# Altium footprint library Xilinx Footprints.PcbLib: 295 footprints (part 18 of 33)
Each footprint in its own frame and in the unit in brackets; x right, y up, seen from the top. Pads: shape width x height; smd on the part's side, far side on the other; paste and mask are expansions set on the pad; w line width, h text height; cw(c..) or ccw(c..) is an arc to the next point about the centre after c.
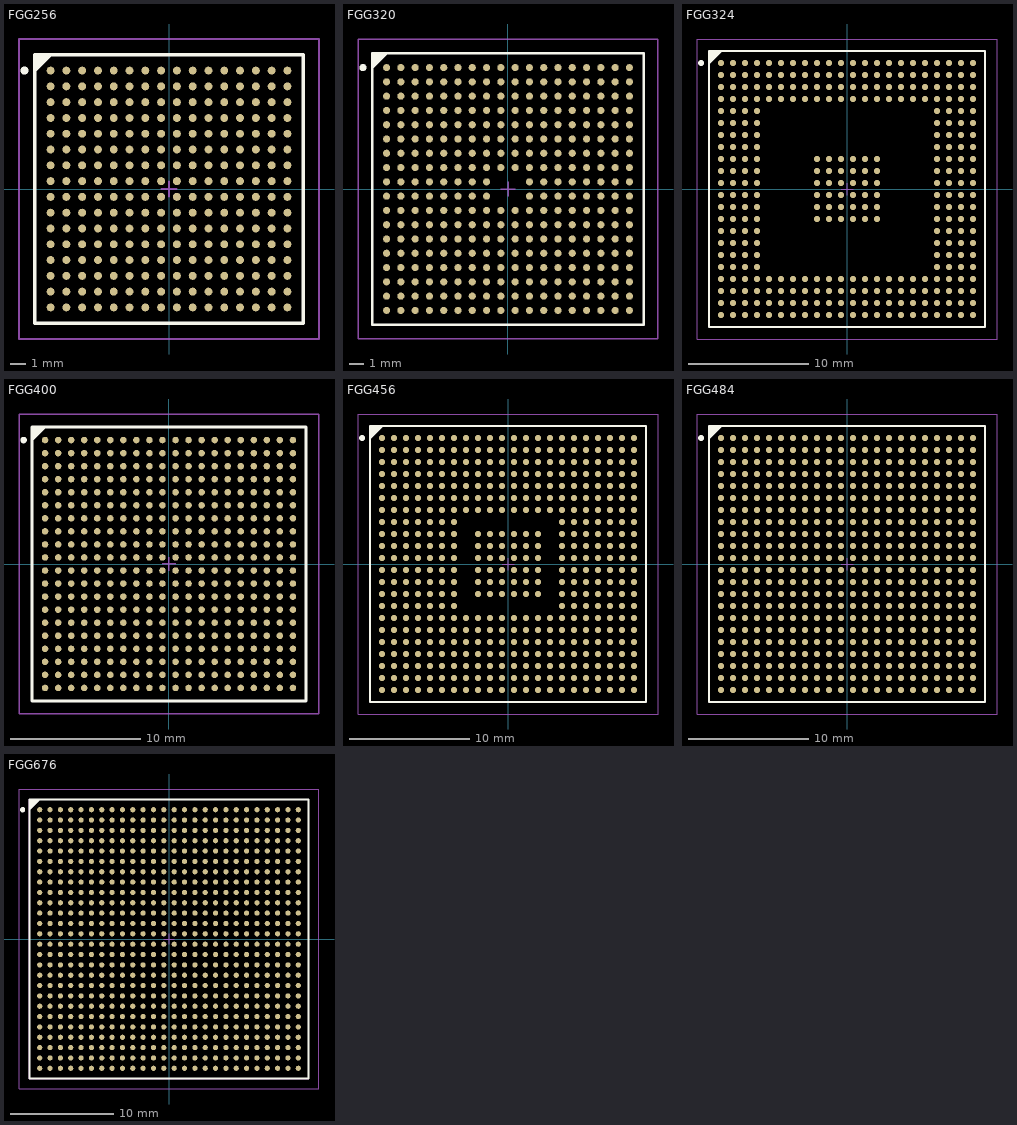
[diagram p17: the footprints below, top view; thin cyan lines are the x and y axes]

## FGG256 [mm] "256-Ball Fine Pitch Ball Grid Array (FGG256) - Pb-Free"
height 2
pads (256):
  round 0.5 smd: A1(-7.5,7.5) A2(-6.5,7.5) A3(-5.5,7.5) A4(-4.5,7.5) A5(-3.5,7.5) A6(-2.5,7.5) A7(-1.5,7.5) A8(-0.5,7.5) A9(0.5,7.5) A10(1.5,7.5) A11(2.5,7.5) A12(3.5,7.5) A13(4.5,7.5) A14(5.5,7.5) A15(6.5,7.5) A16(7.5,7.5) B1(-7.5,6.5) B2(-6.5,6.5) B3(-5.5,6.5) B4(-4.5,6.5) B5(-3.5,6.5) B6(-2.5,6.5) B7(-1.5,6.5) B8(-0.5,6.5) B9(0.5,6.5) B10(1.5,6.5) B11(2.5,6.5) B12(3.5,6.5) B13(4.5,6.5) B14(5.5,6.5) B15(6.5,6.5) B16(7.5,6.5) C1(-7.5,5.5) C2(-6.5,5.5) C3(-5.5,5.5) C4(-4.5,5.5) C5(-3.5,5.5) C6(-2.5,5.5) C7(-1.5,5.5) C8(-0.5,5.5) C9(0.5,5.5) C10(1.5,5.5) C11(2.5,5.5) C12(3.5,5.5) C13(4.5,5.5) C14(5.5,5.5) C15(6.5,5.5) C16(7.5,5.5) D1(-7.5,4.5) D2(-6.5,4.5) D3(-5.5,4.5) D4(-4.5,4.5) D5(-3.5,4.5) D6(-2.5,4.5) D7(-1.5,4.5) D8(-0.5,4.5) D9(0.5,4.5) D10(1.5,4.5) D11(2.5,4.5) D12(3.5,4.5) D13(4.5,4.5) D14(5.5,4.5) D15(6.5,4.5) D16(7.5,4.5) E1(-7.5,3.5) E2(-6.5,3.5) E3(-5.5,3.5) E4(-4.5,3.5) E5(-3.5,3.5) E6(-2.5,3.5) E7(-1.5,3.5) E8(-0.5,3.5) E9(0.5,3.5) E10(1.5,3.5) E11(2.5,3.5) E12(3.5,3.5) E13(4.5,3.5) E14(5.5,3.5) E15(6.5,3.5) E16(7.5,3.5) F1(-7.5,2.5) F2(-6.5,2.5) F3(-5.5,2.5) F4(-4.5,2.5) F5(-3.5,2.5) F6(-2.5,2.5) F7(-1.5,2.5) F8(-0.5,2.5) F9(0.5,2.5) F10(1.5,2.5) F11(2.5,2.5) F12(3.5,2.5) F13(4.5,2.5) F14(5.5,2.5) F15(6.5,2.5) F16(7.5,2.5) G1(-7.5,1.5) G2(-6.5,1.5) G3(-5.5,1.5) G4(-4.5,1.5) G5(-3.5,1.5) G6(-2.5,1.5) G7(-1.5,1.5) G8(-0.5,1.5) G9(0.5,1.5) G10(1.5,1.5) G11(2.5,1.5) G12(3.5,1.5) G13(4.5,1.5) G14(5.5,1.5) G15(6.5,1.5) G16(7.5,1.5) H1(-7.5,0.5) H2(-6.5,0.5) H3(-5.5,0.5) H4(-4.5,0.5) H5(-3.5,0.5) H6(-2.5,0.5) H7(-1.5,0.5) H8(-0.5,0.5) H9(0.5,0.5) H10(1.5,0.5) H11(2.5,0.5) H12(3.5,0.5) H13(4.5,0.5) H14(5.5,0.5) H15(6.5,0.5) H16(7.5,0.5) J1(-7.5,-0.5) J2(-6.5,-0.5) J3(-5.5,-0.5) J4(-4.5,-0.5) J5(-3.5,-0.5) J6(-2.5,-0.5) J7(-1.5,-0.5) J8(-0.5,-0.5) J9(0.5,-0.5) J10(1.5,-0.5) J11(2.5,-0.5) J12(3.5,-0.5) J13(4.5,-0.5) J14(5.5,-0.5) J15(6.5,-0.5) J16(7.5,-0.5) K1(-7.5,-1.5) K2(-6.5,-1.5) K3(-5.5,-1.5) K4(-4.5,-1.5) K5(-3.5,-1.5) K6(-2.5,-1.5) K7(-1.5,-1.5) K8(-0.5,-1.5) K9(0.5,-1.5) K10(1.5,-1.5) K11(2.5,-1.5) K12(3.5,-1.5) K13(4.5,-1.5) K14(5.5,-1.5) K15(6.5,-1.5) K16(7.5,-1.5) L1(-7.5,-2.5) L2(-6.5,-2.5) L3(-5.5,-2.5) L4(-4.5,-2.5) L5(-3.5,-2.5) L6(-2.5,-2.5) L7(-1.5,-2.5) L8(-0.5,-2.5) L9(0.5,-2.5) L10(1.5,-2.5) L11(2.5,-2.5) L12(3.5,-2.5) L13(4.5,-2.5) L14(5.5,-2.5) L15(6.5,-2.5) L16(7.5,-2.5) M1(-7.5,-3.5) M2(-6.5,-3.5) M3(-5.5,-3.5) M4(-4.5,-3.5) M5(-3.5,-3.5) M6(-2.5,-3.5) M7(-1.5,-3.5) M8(-0.5,-3.5) M9(0.5,-3.5) M10(1.5,-3.5) M11(2.5,-3.5) M12(3.5,-3.5) M13(4.5,-3.5) M14(5.5,-3.5) M15(6.5,-3.5) M16(7.5,-3.5) N1(-7.5,-4.5) N2(-6.5,-4.5) N3(-5.5,-4.5) N4(-4.5,-4.5) N5(-3.5,-4.5) N6(-2.5,-4.5) N7(-1.5,-4.5) N8(-0.5,-4.5) N9(0.5,-4.5) N10(1.5,-4.5) N11(2.5,-4.5) N12(3.5,-4.5) N13(4.5,-4.5) N14(5.5,-4.5) N15(6.5,-4.5) N16(7.5,-4.5) P1(-7.5,-5.5) P2(-6.5,-5.5) P3(-5.5,-5.5) P4(-4.5,-5.5) P5(-3.5,-5.5) P6(-2.5,-5.5) P7(-1.5,-5.5) P8(-0.5,-5.5) P9(0.5,-5.5) P10(1.5,-5.5) P11(2.5,-5.5) P12(3.5,-5.5) P13(4.5,-5.5) P14(5.5,-5.5) P15(6.5,-5.5) P16(7.5,-5.5) R1(-7.5,-6.5) R2(-6.5,-6.5) R3(-5.5,-6.5) R4(-4.5,-6.5) R5(-3.5,-6.5) R6(-2.5,-6.5) R7(-1.5,-6.5) R8(-0.5,-6.5) R9(0.5,-6.5) R10(1.5,-6.5) R11(2.5,-6.5) R12(3.5,-6.5) R13(4.5,-6.5) R14(5.5,-6.5) R15(6.5,-6.5) R16(7.5,-6.5) T1(-7.5,-7.5) T2(-6.5,-7.5) T3(-5.5,-7.5) T4(-4.5,-7.5) T5(-3.5,-7.5) T6(-2.5,-7.5) T7(-1.5,-7.5) T8(-0.5,-7.5) T9(0.5,-7.5) T10(1.5,-7.5) T11(2.5,-7.5) T12(3.5,-7.5) T13(4.5,-7.5) T14(5.5,-7.5) T15(6.5,-7.5) T16(7.5,-7.5)
Top Overlay:
  circle w0.25: c-9.15,7.5 r0.125
  region: -7.5,8.5 -8.5,7.5 -8.5,8.5
  lines w0.2: -8.5,7.5 -7.5,8.5 ; -8.5,-8.5 -8.5,8.5 8.5,8.5 8.5,-8.5 -8.5,-8.5
Mechanical 13:
  lines w0.1: -8.5,-8.5 -8.5,8.5 8.5,8.5 8.5,-8.5 -8.5,-8.5
Mechanical 15:
  lines w0.1: -0.5,0 0.5,0 ; 0,-0.5 0,0.5 ; -9.5,-9.5 -9.5,9.5 9.5,9.5 9.5,-9.5 -9.5,-9.5
3D body: height 2, standoff 0, extent -8.5,-8.5 8.5,8.5

## FGG320 [mm] "320-Ball Fine Pitch Ball Grid Array (FGG320) - Pb-Free"
height 2
pads (320):
  round 0.5 smd: A1(-8.5,8.5) A2(-7.5,8.5) A3(-6.5,8.5) A4(-5.5,8.5) A5(-4.5,8.5) A6(-3.5,8.5) A7(-2.5,8.5) A8(-1.5,8.5) A9(-0.5,8.5) A10(0.5,8.5) A11(1.5,8.5) A12(2.5,8.5) A13(3.5,8.5) A14(4.5,8.5) A15(5.5,8.5) A16(6.5,8.5) A17(7.5,8.5) A18(8.5,8.5) B1(-8.5,7.5) B2(-7.5,7.5) B3(-6.5,7.5) B4(-5.5,7.5) B5(-4.5,7.5) B6(-3.5,7.5) B7(-2.5,7.5) B8(-1.5,7.5) B9(-0.5,7.5) B10(0.5,7.5) B11(1.5,7.5) B12(2.5,7.5) B13(3.5,7.5) B14(4.5,7.5) B15(5.5,7.5) B16(6.5,7.5) B17(7.5,7.5) B18(8.5,7.5) C1(-8.5,6.5) C2(-7.5,6.5) C3(-6.5,6.5) C4(-5.5,6.5) C5(-4.5,6.5) C6(-3.5,6.5) C7(-2.5,6.5) C8(-1.5,6.5) C9(-0.5,6.5) C10(0.5,6.5) C11(1.5,6.5) C12(2.5,6.5) C13(3.5,6.5) C14(4.5,6.5) C15(5.5,6.5) C16(6.5,6.5) C17(7.5,6.5) C18(8.5,6.5) D1(-8.5,5.5) D2(-7.5,5.5) D3(-6.5,5.5) D4(-5.5,5.5) D5(-4.5,5.5) D6(-3.5,5.5) D7(-2.5,5.5) D8(-1.5,5.5) D9(-0.5,5.5) D10(0.5,5.5) D11(1.5,5.5) D12(2.5,5.5) D13(3.5,5.5) D14(4.5,5.5) D15(5.5,5.5) D16(6.5,5.5) D17(7.5,5.5) D18(8.5,5.5) E1(-8.5,4.5) E2(-7.5,4.5) E3(-6.5,4.5) E4(-5.5,4.5) E5(-4.5,4.5) E6(-3.5,4.5) E7(-2.5,4.5) E8(-1.5,4.5) E9(-0.5,4.5) E10(0.5,4.5) E11(1.5,4.5) E12(2.5,4.5) E13(3.5,4.5) E14(4.5,4.5) E15(5.5,4.5) E16(6.5,4.5) E17(7.5,4.5) E18(8.5,4.5) F1(-8.5,3.5) F2(-7.5,3.5) F3(-6.5,3.5) F4(-5.5,3.5) F5(-4.5,3.5) F6(-3.5,3.5) F7(-2.5,3.5) F8(-1.5,3.5) F9(-0.5,3.5) F10(0.5,3.5) F11(1.5,3.5) F12(2.5,3.5) F13(3.5,3.5) F14(4.5,3.5) F15(5.5,3.5) F16(6.5,3.5) F17(7.5,3.5) F18(8.5,3.5) G1(-8.5,2.5) G2(-7.5,2.5) G3(-6.5,2.5) G4(-5.5,2.5) G5(-4.5,2.5) G6(-3.5,2.5) G7(-2.5,2.5) G8(-1.5,2.5) G9(-0.5,2.5) G10(0.5,2.5) G11(1.5,2.5) G12(2.5,2.5) G13(3.5,2.5) G14(4.5,2.5) G15(5.5,2.5) G16(6.5,2.5) G17(7.5,2.5) G18(8.5,2.5) H1(-8.5,1.5) H2(-7.5,1.5) H3(-6.5,1.5) H4(-5.5,1.5) H5(-4.5,1.5) H6(-3.5,1.5) H7(-2.5,1.5) H8(-1.5,1.5) H9(-0.5,1.5) H10(0.5,1.5) H11(1.5,1.5) H12(2.5,1.5) H13(3.5,1.5) H14(4.5,1.5) H15(5.5,1.5) H16(6.5,1.5) H17(7.5,1.5) H18(8.5,1.5) J1(-8.5,0.5) J2(-7.5,0.5) J3(-6.5,0.5) J4(-5.5,0.5) J5(-4.5,0.5) J6(-3.5,0.5) J7(-2.5,0.5) J8(-1.5,0.5) J11(1.5,0.5) J12(2.5,0.5) J13(3.5,0.5) J14(4.5,0.5) J15(5.5,0.5) J16(6.5,0.5) J17(7.5,0.5) J18(8.5,0.5) K1(-8.5,-0.5) K2(-7.5,-0.5) K3(-6.5,-0.5) K4(-5.5,-0.5) K5(-4.5,-0.5) K6(-3.5,-0.5) K7(-2.5,-0.5) K8(-1.5,-0.5) K11(1.5,-0.5) K12(2.5,-0.5) K13(3.5,-0.5) K14(4.5,-0.5) K15(5.5,-0.5) K16(6.5,-0.5) K17(7.5,-0.5) K18(8.5,-0.5) L1(-8.5,-1.5) L2(-7.5,-1.5) L3(-6.5,-1.5) L4(-5.5,-1.5) L5(-4.5,-1.5) L6(-3.5,-1.5) L7(-2.5,-1.5) L8(-1.5,-1.5) L9(-0.5,-1.5) L10(0.5,-1.5) L11(1.5,-1.5) L12(2.5,-1.5) L13(3.5,-1.5) L14(4.5,-1.5) L15(5.5,-1.5) L16(6.5,-1.5) L17(7.5,-1.5) L18(8.5,-1.5) M1(-8.5,-2.5) M2(-7.5,-2.5) M3(-6.5,-2.5) M4(-5.5,-2.5) M5(-4.5,-2.5) M6(-3.5,-2.5) M7(-2.5,-2.5) M8(-1.5,-2.5) M9(-0.5,-2.5) M10(0.5,-2.5) M11(1.5,-2.5) M12(2.5,-2.5) M13(3.5,-2.5) M14(4.5,-2.5) M15(5.5,-2.5) M16(6.5,-2.5) M17(7.5,-2.5) M18(8.5,-2.5) N1(-8.5,-3.5) N2(-7.5,-3.5) N3(-6.5,-3.5) N4(-5.5,-3.5) N5(-4.5,-3.5) N6(-3.5,-3.5) N7(-2.5,-3.5) N8(-1.5,-3.5) N9(-0.5,-3.5) N10(0.5,-3.5) N11(1.5,-3.5) N12(2.5,-3.5) N13(3.5,-3.5) N14(4.5,-3.5) N15(5.5,-3.5) N16(6.5,-3.5) N17(7.5,-3.5) N18(8.5,-3.5) P1(-8.5,-4.5) P2(-7.5,-4.5) P3(-6.5,-4.5) P4(-5.5,-4.5) P5(-4.5,-4.5) P6(-3.5,-4.5) P7(-2.5,-4.5) P8(-1.5,-4.5) P9(-0.5,-4.5) P10(0.5,-4.5) P11(1.5,-4.5) P12(2.5,-4.5) P13(3.5,-4.5) P14(4.5,-4.5) P15(5.5,-4.5) P16(6.5,-4.5) P17(7.5,-4.5) P18(8.5,-4.5) R1(-8.5,-5.5) R2(-7.5,-5.5) R3(-6.5,-5.5) R4(-5.5,-5.5) R5(-4.5,-5.5) R6(-3.5,-5.5) R7(-2.5,-5.5) R8(-1.5,-5.5) R9(-0.5,-5.5) R10(0.5,-5.5) R11(1.5,-5.5) R12(2.5,-5.5) R13(3.5,-5.5) R14(4.5,-5.5) R15(5.5,-5.5) R16(6.5,-5.5) R17(7.5,-5.5) R18(8.5,-5.5) T1(-8.5,-6.5) T2(-7.5,-6.5) T3(-6.5,-6.5) T4(-5.5,-6.5) T5(-4.5,-6.5) T6(-3.5,-6.5) T7(-2.5,-6.5) T8(-1.5,-6.5) T9(-0.5,-6.5) T10(0.5,-6.5) T11(1.5,-6.5) T12(2.5,-6.5) T13(3.5,-6.5) T14(4.5,-6.5) T15(5.5,-6.5) T16(6.5,-6.5) T17(7.5,-6.5) T18(8.5,-6.5) U1(-8.5,-7.5) U2(-7.5,-7.5) U3(-6.5,-7.5) U4(-5.5,-7.5) U5(-4.5,-7.5) U6(-3.5,-7.5) U7(-2.5,-7.5) U8(-1.5,-7.5) U9(-0.5,-7.5) U10(0.5,-7.5) U11(1.5,-7.5) U12(2.5,-7.5) U13(3.5,-7.5) U14(4.5,-7.5) U15(5.5,-7.5) U16(6.5,-7.5) U17(7.5,-7.5) U18(8.5,-7.5) V1(-8.5,-8.5) V2(-7.5,-8.5) V3(-6.5,-8.5) V4(-5.5,-8.5) V5(-4.5,-8.5) V6(-3.5,-8.5) V7(-2.5,-8.5) V8(-1.5,-8.5) V9(-0.5,-8.5) V10(0.5,-8.5) V11(1.5,-8.5) V12(2.5,-8.5) V13(3.5,-8.5) V14(4.5,-8.5) V15(5.5,-8.5) V16(6.5,-8.5) V17(7.5,-8.5) V18(8.5,-8.5)
Top Overlay:
  circle w0.25: c-10.15,8.5 r0.125
  region: -8.5,9.5 -9.5,8.5 -9.5,9.5
  lines w0.2: -9.5,8.5 -8.5,9.5 ; -9.5,-9.5 9.5,-9.5 9.5,9.5 -9.5,9.5 -9.5,-9.5
Mechanical 13:
  lines w0.1: -9.5,-9.5 9.5,-9.5 9.5,9.5 -9.5,9.5 -9.5,-9.5
Mechanical 15:
  lines w0.1: -0.5,0 0.5,0 ; 0,-0.5 0,0.5 ; -10.5,-10.5 10.5,-10.5 10.5,10.5 -10.5,10.5 -10.5,-10.5
3D body: height 2, standoff 0, extent -9.5,-9.5 9.5,9.5

## FGG324 [mm] "324-Ball Fine Pitch Ball Grid Array 1.00 mm Pitch (FGG324) - Pb-Free"
height 2.5
pads (324):
  round 0.5 smd: A1(-10.5,10.5) A2(-9.5,10.5) A3(-8.5,10.5) A4(-7.5,10.5) A5(-6.5,10.5) A6(-5.5,10.5) A7(-4.5,10.5) A8(-3.5,10.5) A9(-2.5,10.5) A10(-1.5,10.5) A11(-0.5,10.5) A12(0.5,10.5) A13(1.5,10.5) A14(2.5,10.5) A15(3.5,10.5) A16(4.5,10.5) A17(5.5,10.5) A18(6.5,10.5) A19(7.5,10.5) A20(8.5,10.5) A21(9.5,10.5) A22(10.5,10.5) AA1(-10.5,-9.5) AA2(-9.5,-9.5) AA3(-8.5,-9.5) AA4(-7.5,-9.5) AA5(-6.5,-9.5) AA6(-5.5,-9.5) AA7(-4.5,-9.5) AA8(-3.5,-9.5) AA9(-2.5,-9.5) AA10(-1.5,-9.5) AA11(-0.5,-9.5) AA12(0.5,-9.5) AA13(1.5,-9.5) AA14(2.5,-9.5) AA15(3.5,-9.5) AA16(4.5,-9.5) AA17(5.5,-9.5) AA18(6.5,-9.5) AA19(7.5,-9.5) AA20(8.5,-9.5) AA21(9.5,-9.5) AA22(10.5,-9.5) AB1(-10.5,-10.5) AB2(-9.5,-10.5) AB3(-8.5,-10.5) AB4(-7.5,-10.5) AB5(-6.5,-10.5) AB6(-5.5,-10.5) AB7(-4.5,-10.5) AB8(-3.5,-10.5) AB9(-2.5,-10.5) AB10(-1.5,-10.5) AB11(-0.5,-10.5) AB12(0.5,-10.5) AB13(1.5,-10.5) AB14(2.5,-10.5) AB15(3.5,-10.5) AB16(4.5,-10.5) AB17(5.5,-10.5) AB18(6.5,-10.5) AB19(7.5,-10.5) AB20(8.5,-10.5) AB21(9.5,-10.5) AB22(10.5,-10.5) B1(-10.5,9.5) B2(-9.5,9.5) B3(-8.5,9.5) B4(-7.5,9.5) B5(-6.5,9.5) B6(-5.5,9.5) B7(-4.5,9.5) B8(-3.5,9.5) B9(-2.5,9.5) B10(-1.5,9.5) B11(-0.5,9.5) B12(0.5,9.5) B13(1.5,9.5) B14(2.5,9.5) B15(3.5,9.5) B16(4.5,9.5) B17(5.5,9.5) B18(6.5,9.5) B19(7.5,9.5) B20(8.5,9.5) B21(9.5,9.5) B22(10.5,9.5) C1(-10.5,8.5) C2(-9.5,8.5) C3(-8.5,8.5) C4(-7.5,8.5) C5(-6.5,8.5) C6(-5.5,8.5) C7(-4.5,8.5) C8(-3.5,8.5) C9(-2.5,8.5) C10(-1.5,8.5) C11(-0.5,8.5) C12(0.5,8.5) C13(1.5,8.5) C14(2.5,8.5) C15(3.5,8.5) C16(4.5,8.5) C17(5.5,8.5) C18(6.5,8.5) C19(7.5,8.5) C20(8.5,8.5) C21(9.5,8.5) C22(10.5,8.5) D1(-10.5,7.5) D2(-9.5,7.5) D3(-8.5,7.5) D4(-7.5,7.5) D5(-6.5,7.5) D6(-5.5,7.5) D7(-4.5,7.5) D8(-3.5,7.5) D9(-2.5,7.5) D10(-1.5,7.5) D11(-0.5,7.5) D12(0.5,7.5) D13(1.5,7.5) D14(2.5,7.5) D15(3.5,7.5) D16(4.5,7.5) D17(5.5,7.5) D18(6.5,7.5) D19(7.5,7.5) D20(8.5,7.5) D21(9.5,7.5) D22(10.5,7.5) E1(-10.5,6.5) E2(-9.5,6.5) E3(-8.5,6.5) E4(-7.5,6.5) E19(7.5,6.5) E20(8.5,6.5) E21(9.5,6.5) E22(10.5,6.5) F1(-10.5,5.5) F2(-9.5,5.5) F3(-8.5,5.5) F4(-7.5,5.5) F19(7.5,5.5) F20(8.5,5.5) F21(9.5,5.5) F22(10.5,5.5) G1(-10.5,4.5) G2(-9.5,4.5) G3(-8.5,4.5) G4(-7.5,4.5) G19(7.5,4.5) G20(8.5,4.5) G21(9.5,4.5) G22(10.5,4.5) H1(-10.5,3.5) H2(-9.5,3.5) H3(-8.5,3.5) H4(-7.5,3.5) H19(7.5,3.5) H20(8.5,3.5) H21(9.5,3.5) H22(10.5,3.5) J1(-10.5,2.5) J2(-9.5,2.5) J3(-8.5,2.5) J4(-7.5,2.5) J9(-2.5,2.5) J10(-1.5,2.5) J11(-0.5,2.5) J12(0.5,2.5) J13(1.5,2.5) J14(2.5,2.5) J19(7.5,2.5) J20(8.5,2.5) J21(9.5,2.5) J22(10.5,2.5) K1(-10.5,1.5) K2(-9.5,1.5) K3(-8.5,1.5) K4(-7.5,1.5) K9(-2.5,1.5) K10(-1.5,1.5) K11(-0.5,1.5) K12(0.5,1.5) K13(1.5,1.5) K14(2.5,1.5) K19(7.5,1.5) K20(8.5,1.5) K21(9.5,1.5) K22(10.5,1.5) L1(-10.5,0.5) L2(-9.5,0.5) L3(-8.5,0.5) L4(-7.5,0.5) L9(-2.5,0.5) L10(-1.5,0.5) L11(-0.5,0.5) L12(0.5,0.5) L13(1.5,0.5) L14(2.5,0.5) L19(7.5,0.5) L20(8.5,0.5) L21(9.5,0.5) L22(10.5,0.5) M1(-10.5,-0.5) M2(-9.5,-0.5) M3(-8.5,-0.5) M4(-7.5,-0.5) M9(-2.5,-0.5) M10(-1.5,-0.5) M11(-0.5,-0.5) M12(0.5,-0.5) M13(1.5,-0.5) M14(2.5,-0.5) M19(7.5,-0.5) M20(8.5,-0.5) M21(9.5,-0.5) M22(10.5,-0.5) N1(-10.5,-1.5) N2(-9.5,-1.5) N3(-8.5,-1.5) N4(-7.5,-1.5) N9(-2.5,-1.5) N10(-1.5,-1.5) N11(-0.5,-1.5) N12(0.5,-1.5) N13(1.5,-1.5) N14(2.5,-1.5) N19(7.5,-1.5) N20(8.5,-1.5) N21(9.5,-1.5) N22(10.5,-1.5) P1(-10.5,-2.5) P2(-9.5,-2.5) P3(-8.5,-2.5) P4(-7.5,-2.5) P9(-2.5,-2.5) P10(-1.5,-2.5) P11(-0.5,-2.5) P12(0.5,-2.5) P13(1.5,-2.5) P14(2.5,-2.5) P19(7.5,-2.5) P20(8.5,-2.5) P21(9.5,-2.5) P22(10.5,-2.5) R1(-10.5,-3.5) R2(-9.5,-3.5) R3(-8.5,-3.5) R4(-7.5,-3.5) R19(7.5,-3.5) R20(8.5,-3.5) R21(9.5,-3.5) R22(10.5,-3.5) T1(-10.5,-4.5) T2(-9.5,-4.5) T3(-8.5,-4.5) T4(-7.5,-4.5) T19(7.5,-4.5) T20(8.5,-4.5) T21(9.5,-4.5) T22(10.5,-4.5) U1(-10.5,-5.5) U2(-9.5,-5.5) U3(-8.5,-5.5) U4(-7.5,-5.5) U19(7.5,-5.5) U20(8.5,-5.5) U21(9.5,-5.5) U22(10.5,-5.5) V1(-10.5,-6.5) V2(-9.5,-6.5) V3(-8.5,-6.5) V4(-7.5,-6.5) V19(7.5,-6.5) V20(8.5,-6.5) V21(9.5,-6.5) V22(10.5,-6.5) W1(-10.5,-7.5) W2(-9.5,-7.5) W3(-8.5,-7.5) W4(-7.5,-7.5) W5(-6.5,-7.5) W6(-5.5,-7.5) W7(-4.5,-7.5) W8(-3.5,-7.5) W9(-2.5,-7.5) W10(-1.5,-7.5) W11(-0.5,-7.5) W12(0.5,-7.5) W13(1.5,-7.5) W14(2.5,-7.5) W15(3.5,-7.5) W16(4.5,-7.5) W17(5.5,-7.5) W18(6.5,-7.5) W19(7.5,-7.5) W20(8.5,-7.5) W21(9.5,-7.5) W22(10.5,-7.5) Y1(-10.5,-8.5) Y2(-9.5,-8.5) Y3(-8.5,-8.5) Y4(-7.5,-8.5) Y5(-6.5,-8.5) Y6(-5.5,-8.5) Y7(-4.5,-8.5) Y8(-3.5,-8.5) Y9(-2.5,-8.5) Y10(-1.5,-8.5) Y11(-0.5,-8.5) Y12(0.5,-8.5) Y13(1.5,-8.5) Y14(2.5,-8.5) Y15(3.5,-8.5) Y16(4.5,-8.5) Y17(5.5,-8.5) Y18(6.5,-8.5) Y19(7.5,-8.5) Y20(8.5,-8.5) Y21(9.5,-8.5) Y22(10.5,-8.5)
Top Overlay:
  circle w0.25: c-12.15,10.5 r0.125
  region: -10.5,11.5 -11.5,10.5 -11.5,11.5
  lines w0.2: -11.5,10.5 -10.5,11.5 ; -11.5,-11.5 11.5,-11.5 11.5,11.5 -11.5,11.5 -11.5,-11.5
Mechanical 13:
  lines w0.1: -11.5,-11.5 11.5,-11.5 11.5,11.5 -11.5,11.5 -11.5,-11.5
Mechanical 15:
  lines w0.1: -0.5,0 0.5,0 ; 0,-0.5 0,0.5 ; -12.5,-12.5 12.5,-12.5 12.5,12.5 -12.5,12.5 -12.5,-12.5
3D body: height 2.5, standoff 0, extent -11.5,-11.5 11.5,11.5

## FGG400 [mm] "400-Ball Fine Pitch Ball Grid Array 1.00 mm Pitch (FGG400) - Pb-Free"
height 2.43
pads (400):
  round 0.5 smd: A1(-9.5,9.5) A2(-8.5,9.5) A3(-7.5,9.5) A4(-6.5,9.5) A5(-5.5,9.5) A6(-4.5,9.5) A7(-3.5,9.5) A8(-2.5,9.5) A9(-1.5,9.5) A10(-0.5,9.5) A11(0.5,9.5) A12(1.5,9.5) A13(2.5,9.5) A14(3.5,9.5) A15(4.5,9.5) A16(5.5,9.5) A17(6.5,9.5) A18(7.5,9.5) A19(8.5,9.5) A20(9.5,9.5) B1(-9.5,8.5) B2(-8.5,8.5) B3(-7.5,8.5) B4(-6.5,8.5) B5(-5.5,8.5) B6(-4.5,8.5) B7(-3.5,8.5) B8(-2.5,8.5) B9(-1.5,8.5) B10(-0.5,8.5) B11(0.5,8.5) B12(1.5,8.5) B13(2.5,8.5) B14(3.5,8.5) B15(4.5,8.5) B16(5.5,8.5) B17(6.5,8.5) B18(7.5,8.5) B19(8.5,8.5) B20(9.5,8.5) C1(-9.5,7.5) C2(-8.5,7.5) C3(-7.5,7.5) C4(-6.5,7.5) C5(-5.5,7.5) C6(-4.5,7.5) C7(-3.5,7.5) C8(-2.5,7.5) C9(-1.5,7.5) C10(-0.5,7.5) C11(0.5,7.5) C12(1.5,7.5) C13(2.5,7.5) C14(3.5,7.5) C15(4.5,7.5) C16(5.5,7.5) C17(6.5,7.5) C18(7.5,7.5) C19(8.5,7.5) C20(9.5,7.5) D1(-9.5,6.5) D2(-8.5,6.5) D3(-7.5,6.5) D4(-6.5,6.5) D5(-5.5,6.5) D6(-4.5,6.5) D7(-3.5,6.5) D8(-2.5,6.5) D9(-1.5,6.5) D10(-0.5,6.5) D11(0.5,6.5) D12(1.5,6.5) D13(2.5,6.5) D14(3.5,6.5) D15(4.5,6.5) D16(5.5,6.5) D17(6.5,6.5) D18(7.5,6.5) D19(8.5,6.5) D20(9.5,6.5) E1(-9.5,5.5) E2(-8.5,5.5) E3(-7.5,5.5) E4(-6.5,5.5) E5(-5.5,5.5) E6(-4.5,5.5) E7(-3.5,5.5) E8(-2.5,5.5) E9(-1.5,5.5) E10(-0.5,5.5) E11(0.5,5.5) E12(1.5,5.5) E13(2.5,5.5) E14(3.5,5.5) E15(4.5,5.5) E16(5.5,5.5) E17(6.5,5.5) E18(7.5,5.5) E19(8.5,5.5) E20(9.5,5.5) F1(-9.5,4.5) F2(-8.5,4.5) F3(-7.5,4.5) F4(-6.5,4.5) F5(-5.5,4.5) F6(-4.5,4.5) F7(-3.5,4.5) F8(-2.5,4.5) F9(-1.5,4.5) F10(-0.5,4.5) F11(0.5,4.5) F12(1.5,4.5) F13(2.5,4.5) F14(3.5,4.5) F15(4.5,4.5) F16(5.5,4.5) F17(6.5,4.5) F18(7.5,4.5) F19(8.5,4.5) F20(9.5,4.5) G1(-9.5,3.5) G2(-8.5,3.5) G3(-7.5,3.5) G4(-6.5,3.5) G5(-5.5,3.5) G6(-4.5,3.5) G7(-3.5,3.5) G8(-2.5,3.5) G9(-1.5,3.5) G10(-0.5,3.5) G11(0.5,3.5) G12(1.5,3.5) G13(2.5,3.5) G14(3.5,3.5) G15(4.5,3.5) G16(5.5,3.5) G17(6.5,3.5) G18(7.5,3.5) G19(8.5,3.5) G20(9.5,3.5) H1(-9.5,2.5) H2(-8.5,2.5) H3(-7.5,2.5) H4(-6.5,2.5) H5(-5.5,2.5) H6(-4.5,2.5) H7(-3.5,2.5) H8(-2.5,2.5) H9(-1.5,2.5) H10(-0.5,2.5) H11(0.5,2.5) H12(1.5,2.5) H13(2.5,2.5) H14(3.5,2.5) H15(4.5,2.5) H16(5.5,2.5) H17(6.5,2.5) H18(7.5,2.5) H19(8.5,2.5) H20(9.5,2.5) J1(-9.5,1.5) J2(-8.5,1.5) J3(-7.5,1.5) J4(-6.5,1.5) J5(-5.5,1.5) J6(-4.5,1.5) J7(-3.5,1.5) J8(-2.5,1.5) J9(-1.5,1.5) J10(-0.5,1.5) J11(0.5,1.5) J12(1.5,1.5) J13(2.5,1.5) J14(3.5,1.5) J15(4.5,1.5) J16(5.5,1.5) J17(6.5,1.5) J18(7.5,1.5) J19(8.5,1.5) J20(9.5,1.5) K1(-9.5,0.5) K2(-8.5,0.5) K3(-7.5,0.5) K4(-6.5,0.5) K5(-5.5,0.5) K6(-4.5,0.5) K7(-3.5,0.5) K8(-2.5,0.5) K9(-1.5,0.5) K10(-0.5,0.5) K11(0.5,0.5) K12(1.5,0.5) K13(2.5,0.5) K14(3.5,0.5) K15(4.5,0.5) K16(5.5,0.5) K17(6.5,0.5) K18(7.5,0.5) K19(8.5,0.5) K20(9.5,0.5) L1(-9.5,-0.5) L2(-8.5,-0.5) L3(-7.5,-0.5) L4(-6.5,-0.5) L5(-5.5,-0.5) L6(-4.5,-0.5) L7(-3.5,-0.5) L8(-2.5,-0.5) L9(-1.5,-0.5) L10(-0.5,-0.5) L11(0.5,-0.5) L12(1.5,-0.5) L13(2.5,-0.5) L14(3.5,-0.5) L15(4.5,-0.5) L16(5.5,-0.5) L17(6.5,-0.5) L18(7.5,-0.5) L19(8.5,-0.5) L20(9.5,-0.5) M1(-9.5,-1.5) M2(-8.5,-1.5) M3(-7.5,-1.5) M4(-6.5,-1.5) M5(-5.5,-1.5) M6(-4.5,-1.5) M7(-3.5,-1.5) M8(-2.5,-1.5) M9(-1.5,-1.5) M10(-0.5,-1.5) M11(0.5,-1.5) M12(1.5,-1.5) M13(2.5,-1.5) M14(3.5,-1.5) M15(4.5,-1.5) M16(5.5,-1.5) M17(6.5,-1.5) M18(7.5,-1.5) M19(8.5,-1.5) M20(9.5,-1.5) N1(-9.5,-2.5) N2(-8.5,-2.5) N3(-7.5,-2.5) N4(-6.5,-2.5) N5(-5.5,-2.5) N6(-4.5,-2.5) N7(-3.5,-2.5) N8(-2.5,-2.5) N9(-1.5,-2.5) N10(-0.5,-2.5) N11(0.5,-2.5) N12(1.5,-2.5) N13(2.5,-2.5) N14(3.5,-2.5) N15(4.5,-2.5) N16(5.5,-2.5) N17(6.5,-2.5) N18(7.5,-2.5) N19(8.5,-2.5) N20(9.5,-2.5) P1(-9.5,-3.5) P2(-8.5,-3.5) P3(-7.5,-3.5) P4(-6.5,-3.5) P5(-5.5,-3.5) P6(-4.5,-3.5) P7(-3.5,-3.5) P8(-2.5,-3.5) P9(-1.5,-3.5) P10(-0.5,-3.5) P11(0.5,-3.5) P12(1.5,-3.5) P13(2.5,-3.5) P14(3.5,-3.5) P15(4.5,-3.5) P16(5.5,-3.5) P17(6.5,-3.5) P18(7.5,-3.5) P19(8.5,-3.5) P20(9.5,-3.5) R1(-9.5,-4.5) R2(-8.5,-4.5) R3(-7.5,-4.5) R4(-6.5,-4.5) R5(-5.5,-4.5) R6(-4.5,-4.5) R7(-3.5,-4.5) R8(-2.5,-4.5) R9(-1.5,-4.5) R10(-0.5,-4.5) R11(0.5,-4.5) R12(1.5,-4.5) R13(2.5,-4.5) R14(3.5,-4.5) R15(4.5,-4.5) R16(5.5,-4.5) R17(6.5,-4.5) R18(7.5,-4.5) R19(8.5,-4.5) R20(9.5,-4.5) T1(-9.5,-5.5) T2(-8.5,-5.5) T3(-7.5,-5.5) T4(-6.5,-5.5) T5(-5.5,-5.5) T6(-4.5,-5.5) T7(-3.5,-5.5) T8(-2.5,-5.5) T9(-1.5,-5.5) T10(-0.5,-5.5) T11(0.5,-5.5) T12(1.5,-5.5) T13(2.5,-5.5) T14(3.5,-5.5) T15(4.5,-5.5) T16(5.5,-5.5) T17(6.5,-5.5) T18(7.5,-5.5) T19(8.5,-5.5) T20(9.5,-5.5) U1(-9.5,-6.5) U2(-8.5,-6.5) U3(-7.5,-6.5) U4(-6.5,-6.5) U5(-5.5,-6.5) U6(-4.5,-6.5) U7(-3.5,-6.5) U8(-2.5,-6.5) U9(-1.5,-6.5) U10(-0.5,-6.5) U11(0.5,-6.5) U12(1.5,-6.5) U13(2.5,-6.5) U14(3.5,-6.5) U15(4.5,-6.5) U16(5.5,-6.5) U17(6.5,-6.5) U18(7.5,-6.5) U19(8.5,-6.5) U20(9.5,-6.5) V1(-9.5,-7.5) V2(-8.5,-7.5) V3(-7.5,-7.5) V4(-6.5,-7.5) V5(-5.5,-7.5) V6(-4.5,-7.5) V7(-3.5,-7.5) V8(-2.5,-7.5) V9(-1.5,-7.5) V10(-0.5,-7.5) V11(0.5,-7.5) V12(1.5,-7.5) V13(2.5,-7.5) V14(3.5,-7.5) V15(4.5,-7.5) V16(5.5,-7.5) V17(6.5,-7.5) V18(7.5,-7.5) V19(8.5,-7.5) V20(9.5,-7.5) W1(-9.5,-8.5) W2(-8.5,-8.5) W3(-7.5,-8.5) W4(-6.5,-8.5) W5(-5.5,-8.5) W6(-4.5,-8.5) W7(-3.5,-8.5) W8(-2.5,-8.5) W9(-1.5,-8.5) W10(-0.5,-8.5) W11(0.5,-8.5) W12(1.5,-8.5) W13(2.5,-8.5) W14(3.5,-8.5) W15(4.5,-8.5) W16(5.5,-8.5) W17(6.5,-8.5) W18(7.5,-8.5) W19(8.5,-8.5) W20(9.5,-8.5) Y1(-9.5,-9.5) Y2(-8.5,-9.5) Y3(-7.5,-9.5) Y4(-6.5,-9.5) Y5(-5.5,-9.5) Y6(-4.5,-9.5) Y7(-3.5,-9.5) Y8(-2.5,-9.5) Y9(-1.5,-9.5) Y10(-0.5,-9.5) Y11(0.5,-9.5) Y12(1.5,-9.5) Y13(2.5,-9.5) Y14(3.5,-9.5) Y15(4.5,-9.5) Y16(5.5,-9.5) Y17(6.5,-9.5) Y18(7.5,-9.5) Y19(8.5,-9.5) Y20(9.5,-9.5)
Top Overlay:
  circle w0.25: c-11.15,9.5 r0.125
  region: -9.5,10.5 -10.5,9.5 -10.5,10.5
  lines w0.2: -10.5,9.5 -9.5,10.5 ; -10.5,-10.5 -10.5,10.5 10.5,10.5 10.5,-10.5 -10.5,-10.5
Mechanical 13:
  lines w0.1: -10.5,-10.5 -10.5,10.5 10.5,10.5 10.5,-10.5 -10.5,-10.5
Mechanical 15:
  lines w0.1: -0.5,0 0.5,0 ; 0,-0.5 0,0.5 ; -11.5,-11.5 -11.5,11.5 11.5,11.5 11.5,-11.5 -11.5,-11.5
3D body: height 2.43, standoff 0, extent -10.5,-10.5 10.5,10.5

## FGG456 [mm] "456-Ball Fine Pitch Ball Grid Array (FGG456) - Pb-Free"
height 2.6
pads (456):
  round 0.5 smd: A1(-10.5,10.5) A2(-9.5,10.5) A3(-8.5,10.5) A4(-7.5,10.5) A5(-6.5,10.5) A6(-5.5,10.5) A7(-4.5,10.5) A8(-3.5,10.5) A9(-2.5,10.5) A10(-1.5,10.5) A11(-0.5,10.5) A12(0.5,10.5) A13(1.5,10.5) A14(2.5,10.5) A15(3.5,10.5) A16(4.5,10.5) A17(5.5,10.5) A18(6.5,10.5) A19(7.5,10.5) A20(8.5,10.5) A21(9.5,10.5) A22(10.5,10.5) AA1(-10.5,-9.5) AA2(-9.5,-9.5) AA3(-8.5,-9.5) AA4(-7.5,-9.5) AA5(-6.5,-9.5) AA6(-5.5,-9.5) AA7(-4.5,-9.5) AA8(-3.5,-9.5) AA9(-2.5,-9.5) AA10(-1.5,-9.5) AA11(-0.5,-9.5) AA12(0.5,-9.5) AA13(1.5,-9.5) AA14(2.5,-9.5) AA15(3.5,-9.5) AA16(4.5,-9.5) AA17(5.5,-9.5) AA18(6.5,-9.5) AA19(7.5,-9.5) AA20(8.5,-9.5) AA21(9.5,-9.5) AA22(10.5,-9.5) AB1(-10.5,-10.5) AB2(-9.5,-10.5) AB3(-8.5,-10.5) AB4(-7.5,-10.5) AB5(-6.5,-10.5) AB6(-5.5,-10.5) AB7(-4.5,-10.5) AB8(-3.5,-10.5) AB9(-2.5,-10.5) AB10(-1.5,-10.5) AB11(-0.5,-10.5) AB12(0.5,-10.5) AB13(1.5,-10.5) AB14(2.5,-10.5) AB15(3.5,-10.5) AB16(4.5,-10.5) AB17(5.5,-10.5) AB18(6.5,-10.5) AB19(7.5,-10.5) AB20(8.5,-10.5) AB21(9.5,-10.5) AB22(10.5,-10.5) B1(-10.5,9.5) B2(-9.5,9.5) B3(-8.5,9.5) B4(-7.5,9.5) B5(-6.5,9.5) B6(-5.5,9.5) B7(-4.5,9.5) B8(-3.5,9.5) B9(-2.5,9.5) B10(-1.5,9.5) B11(-0.5,9.5) B12(0.5,9.5) B13(1.5,9.5) B14(2.5,9.5) B15(3.5,9.5) B16(4.5,9.5) B17(5.5,9.5) B18(6.5,9.5) B19(7.5,9.5) B20(8.5,9.5) B21(9.5,9.5) B22(10.5,9.5) C1(-10.5,8.5) C2(-9.5,8.5) C3(-8.5,8.5) C4(-7.5,8.5) C5(-6.5,8.5) C6(-5.5,8.5) C7(-4.5,8.5) C8(-3.5,8.5) C9(-2.5,8.5) C10(-1.5,8.5) C11(-0.5,8.5) C12(0.5,8.5) C13(1.5,8.5) C14(2.5,8.5) C15(3.5,8.5) C16(4.5,8.5) C17(5.5,8.5) C18(6.5,8.5) C19(7.5,8.5) C20(8.5,8.5) C21(9.5,8.5) C22(10.5,8.5) D1(-10.5,7.5) D2(-9.5,7.5) D3(-8.5,7.5) D4(-7.5,7.5) D5(-6.5,7.5) D6(-5.5,7.5) D7(-4.5,7.5) D8(-3.5,7.5) D9(-2.5,7.5) D10(-1.5,7.5) D11(-0.5,7.5) D12(0.5,7.5) D13(1.5,7.5) D14(2.5,7.5) D15(3.5,7.5) D16(4.5,7.5) D17(5.5,7.5) D18(6.5,7.5) D19(7.5,7.5) D20(8.5,7.5) D21(9.5,7.5) D22(10.5,7.5) E1(-10.5,6.5) E2(-9.5,6.5) E3(-8.5,6.5) E4(-7.5,6.5) E5(-6.5,6.5) E6(-5.5,6.5) E7(-4.5,6.5) E8(-3.5,6.5) E9(-2.5,6.5) E10(-1.5,6.5) E11(-0.5,6.5) E12(0.5,6.5) E13(1.5,6.5) E14(2.5,6.5) E15(3.5,6.5) E16(4.5,6.5) E17(5.5,6.5) E18(6.5,6.5) E19(7.5,6.5) E20(8.5,6.5) E21(9.5,6.5) E22(10.5,6.5) F1(-10.5,5.5) F2(-9.5,5.5) F3(-8.5,5.5) F4(-7.5,5.5) F5(-6.5,5.5) F6(-5.5,5.5) F7(-4.5,5.5) F8(-3.5,5.5) F9(-2.5,5.5) F10(-1.5,5.5) F11(-0.5,5.5) F12(0.5,5.5) F13(1.5,5.5) F14(2.5,5.5) F15(3.5,5.5) F16(4.5,5.5) F17(5.5,5.5) F18(6.5,5.5) F19(7.5,5.5) F20(8.5,5.5) F21(9.5,5.5) F22(10.5,5.5) G1(-10.5,4.5) G2(-9.5,4.5) G3(-8.5,4.5) G4(-7.5,4.5) G5(-6.5,4.5) G6(-5.5,4.5) G7(-4.5,4.5) G8(-3.5,4.5) G9(-2.5,4.5) G10(-1.5,4.5) G11(-0.5,4.5) G12(0.5,4.5) G13(1.5,4.5) G14(2.5,4.5) G15(3.5,4.5) G16(4.5,4.5) G17(5.5,4.5) G18(6.5,4.5) G19(7.5,4.5) G20(8.5,4.5) G21(9.5,4.5) G22(10.5,4.5) H1(-10.5,3.5) H2(-9.5,3.5) H3(-8.5,3.5) H4(-7.5,3.5) H5(-6.5,3.5) H6(-5.5,3.5) H7(-4.5,3.5) H16(4.5,3.5) H17(5.5,3.5) H18(6.5,3.5) H19(7.5,3.5) H20(8.5,3.5) H21(9.5,3.5) H22(10.5,3.5) J1(-10.5,2.5) J2(-9.5,2.5) J3(-8.5,2.5) J4(-7.5,2.5) J5(-6.5,2.5) J6(-5.5,2.5) J7(-4.5,2.5) J9(-2.5,2.5) J10(-1.5,2.5) J11(-0.5,2.5) J12(0.5,2.5) J13(1.5,2.5) J14(2.5,2.5) J16(4.5,2.5) J17(5.5,2.5) J18(6.5,2.5) J19(7.5,2.5) J20(8.5,2.5) J21(9.5,2.5) J22(10.5,2.5) K1(-10.5,1.5) K2(-9.5,1.5) K3(-8.5,1.5) K4(-7.5,1.5) K5(-6.5,1.5) K6(-5.5,1.5) K7(-4.5,1.5) K9(-2.5,1.5) K10(-1.5,1.5) K11(-0.5,1.5) K12(0.5,1.5) K13(1.5,1.5) K14(2.5,1.5) K16(4.5,1.5) K17(5.5,1.5) K18(6.5,1.5) K19(7.5,1.5) K20(8.5,1.5) K21(9.5,1.5) K22(10.5,1.5) L1(-10.5,0.5) L2(-9.5,0.5) L3(-8.5,0.5) L4(-7.5,0.5) L5(-6.5,0.5) L6(-5.5,0.5) L7(-4.5,0.5) L9(-2.5,0.5) L10(-1.5,0.5) L11(-0.5,0.5) L12(0.5,0.5) L13(1.5,0.5) L14(2.5,0.5) L16(4.5,0.5) L17(5.5,0.5) L18(6.5,0.5) L19(7.5,0.5) L20(8.5,0.5) L21(9.5,0.5) L22(10.5,0.5) M1(-10.5,-0.5) M2(-9.5,-0.5) M3(-8.5,-0.5) M4(-7.5,-0.5) M5(-6.5,-0.5) M6(-5.5,-0.5) M7(-4.5,-0.5) M9(-2.5,-0.5) M10(-1.5,-0.5) M11(-0.5,-0.5) M12(0.5,-0.5) M13(1.5,-0.5) M14(2.5,-0.5) M16(4.5,-0.5) M17(5.5,-0.5) M18(6.5,-0.5) M19(7.5,-0.5) M20(8.5,-0.5) M21(9.5,-0.5) M22(10.5,-0.5) N1(-10.5,-1.5) N2(-9.5,-1.5) N3(-8.5,-1.5) N4(-7.5,-1.5) N5(-6.5,-1.5) N6(-5.5,-1.5) N7(-4.5,-1.5) N9(-2.5,-1.5) N10(-1.5,-1.5) N11(-0.5,-1.5) N12(0.5,-1.5) N13(1.5,-1.5) N14(2.5,-1.5) N16(4.5,-1.5) N17(5.5,-1.5) N18(6.5,-1.5) N19(7.5,-1.5) N20(8.5,-1.5) N21(9.5,-1.5) N22(10.5,-1.5) P1(-10.5,-2.5) P2(-9.5,-2.5) P3(-8.5,-2.5) P4(-7.5,-2.5) P5(-6.5,-2.5) P6(-5.5,-2.5) P7(-4.5,-2.5) P9(-2.5,-2.5) P10(-1.5,-2.5) P11(-0.5,-2.5) P12(0.5,-2.5) P13(1.5,-2.5) P14(2.5,-2.5) P16(4.5,-2.5) P17(5.5,-2.5) P18(6.5,-2.5) P19(7.5,-2.5) P20(8.5,-2.5) P21(9.5,-2.5) P22(10.5,-2.5) R1(-10.5,-3.5) R2(-9.5,-3.5) R3(-8.5,-3.5) R4(-7.5,-3.5) R5(-6.5,-3.5) R6(-5.5,-3.5) R7(-4.5,-3.5) R16(4.5,-3.5) R17(5.5,-3.5) R18(6.5,-3.5) R19(7.5,-3.5) R20(8.5,-3.5) R21(9.5,-3.5) R22(10.5,-3.5) T1(-10.5,-4.5) T2(-9.5,-4.5) T3(-8.5,-4.5) T4(-7.5,-4.5) T5(-6.5,-4.5) T6(-5.5,-4.5) T7(-4.5,-4.5) T8(-3.5,-4.5) T9(-2.5,-4.5) T10(-1.5,-4.5) T11(-0.5,-4.5) T12(0.5,-4.5) T13(1.5,-4.5) T14(2.5,-4.5) T15(3.5,-4.5) T16(4.5,-4.5) T17(5.5,-4.5) T18(6.5,-4.5) T19(7.5,-4.5) T20(8.5,-4.5) T21(9.5,-4.5) T22(10.5,-4.5) U1(-10.5,-5.5) U2(-9.5,-5.5) U3(-8.5,-5.5) U4(-7.5,-5.5) U5(-6.5,-5.5) U6(-5.5,-5.5) U7(-4.5,-5.5) U8(-3.5,-5.5) U9(-2.5,-5.5) U10(-1.5,-5.5) U11(-0.5,-5.5) U12(0.5,-5.5) U13(1.5,-5.5) U14(2.5,-5.5) U15(3.5,-5.5) U16(4.5,-5.5) U17(5.5,-5.5) U18(6.5,-5.5) U19(7.5,-5.5) U20(8.5,-5.5) U21(9.5,-5.5) U22(10.5,-5.5) V1(-10.5,-6.5) V2(-9.5,-6.5) V3(-8.5,-6.5) V4(-7.5,-6.5) V5(-6.5,-6.5) V6(-5.5,-6.5) V7(-4.5,-6.5) V8(-3.5,-6.5) V9(-2.5,-6.5) V10(-1.5,-6.5) V11(-0.5,-6.5) V12(0.5,-6.5) V13(1.5,-6.5) V14(2.5,-6.5) V15(3.5,-6.5) V16(4.5,-6.5) V17(5.5,-6.5) V18(6.5,-6.5) V19(7.5,-6.5) V20(8.5,-6.5) V21(9.5,-6.5) V22(10.5,-6.5) W1(-10.5,-7.5) W2(-9.5,-7.5) W3(-8.5,-7.5) W4(-7.5,-7.5) W5(-6.5,-7.5) W6(-5.5,-7.5) W7(-4.5,-7.5) W8(-3.5,-7.5) W9(-2.5,-7.5) W10(-1.5,-7.5) W11(-0.5,-7.5) W12(0.5,-7.5) W13(1.5,-7.5) W14(2.5,-7.5) W15(3.5,-7.5) W16(4.5,-7.5) W17(5.5,-7.5) W18(6.5,-7.5) W19(7.5,-7.5) W20(8.5,-7.5) W21(9.5,-7.5) W22(10.5,-7.5) Y1(-10.5,-8.5) Y2(-9.5,-8.5) Y3(-8.5,-8.5) Y4(-7.5,-8.5) Y5(-6.5,-8.5) Y6(-5.5,-8.5) Y7(-4.5,-8.5) Y8(-3.5,-8.5) Y9(-2.5,-8.5) Y10(-1.5,-8.5) Y11(-0.5,-8.5) Y12(0.5,-8.5) Y13(1.5,-8.5) Y14(2.5,-8.5) Y15(3.5,-8.5) Y16(4.5,-8.5) Y17(5.5,-8.5) Y18(6.5,-8.5) Y19(7.5,-8.5) Y20(8.5,-8.5) Y21(9.5,-8.5) Y22(10.5,-8.5)
Top Overlay:
  circle w0.25: c-12.15,10.5 r0.125
  region: -10.5,11.5 -11.5,10.5 -11.5,11.5
  lines w0.2: -11.5,10.5 -10.5,11.5 ; -11.5,-11.5 11.5,-11.5 11.5,11.5 -11.5,11.5 -11.5,-11.5
Mechanical 13:
  lines w0.1: -11.5,-11.5 11.5,-11.5 11.5,11.5 -11.5,11.5 -11.5,-11.5
Mechanical 15:
  lines w0.1: -0.5,0 0.5,0 ; 0,-0.5 0,0.5 ; -12.5,-12.5 12.5,-12.5 12.5,12.5 -12.5,12.5 -12.5,-12.5
3D body: height 2.6, standoff 0, extent -11.5,-11.5 11.5,11.5

## FGG484 [mm] "484-Ball Fine Pitch Ball Grid Array 1.00 mm Pitch (FGG484) - Pb-Free"
height 2.6
pads (484):
  round 0.5 smd: A1(-10.5,10.5) A2(-9.5,10.5) A3(-8.5,10.5) A4(-7.5,10.5) A5(-6.5,10.5) A6(-5.5,10.5) A7(-4.5,10.5) A8(-3.5,10.5) A9(-2.5,10.5) A10(-1.5,10.5) A11(-0.5,10.5) A12(0.5,10.5) A13(1.5,10.5) A14(2.5,10.5) A15(3.5,10.5) A16(4.5,10.5) A17(5.5,10.5) A18(6.5,10.5) A19(7.5,10.5) A20(8.5,10.5) A21(9.5,10.5) A22(10.5,10.5) AA1(-10.5,-9.5) AA2(-9.5,-9.5) AA3(-8.5,-9.5) AA4(-7.5,-9.5) AA5(-6.5,-9.5) AA6(-5.5,-9.5) AA7(-4.5,-9.5) AA8(-3.5,-9.5) AA9(-2.5,-9.5) AA10(-1.5,-9.5) AA11(-0.5,-9.5) AA12(0.5,-9.5) AA13(1.5,-9.5) AA14(2.5,-9.5) AA15(3.5,-9.5) AA16(4.5,-9.5) AA17(5.5,-9.5) AA18(6.5,-9.5) AA19(7.5,-9.5) AA20(8.5,-9.5) AA21(9.5,-9.5) AA22(10.5,-9.5) AB1(-10.5,-10.5) AB2(-9.5,-10.5) AB3(-8.5,-10.5) AB4(-7.5,-10.5) AB5(-6.5,-10.5) AB6(-5.5,-10.5) AB7(-4.5,-10.5) AB8(-3.5,-10.5) AB9(-2.5,-10.5) AB10(-1.5,-10.5) AB11(-0.5,-10.5) AB12(0.5,-10.5) AB13(1.5,-10.5) AB14(2.5,-10.5) AB15(3.5,-10.5) AB16(4.5,-10.5) AB17(5.5,-10.5) AB18(6.5,-10.5) AB19(7.5,-10.5) AB20(8.5,-10.5) AB21(9.5,-10.5) AB22(10.5,-10.5) B1(-10.5,9.5) B2(-9.5,9.5) B3(-8.5,9.5) B4(-7.5,9.5) B5(-6.5,9.5) B6(-5.5,9.5) B7(-4.5,9.5) B8(-3.5,9.5) B9(-2.5,9.5) B10(-1.5,9.5) B11(-0.5,9.5) B12(0.5,9.5) B13(1.5,9.5) B14(2.5,9.5) B15(3.5,9.5) B16(4.5,9.5) B17(5.5,9.5) B18(6.5,9.5) B19(7.5,9.5) B20(8.5,9.5) B21(9.5,9.5) B22(10.5,9.5) C1(-10.5,8.5) C2(-9.5,8.5) C3(-8.5,8.5) C4(-7.5,8.5) C5(-6.5,8.5) C6(-5.5,8.5) C7(-4.5,8.5) C8(-3.5,8.5) C9(-2.5,8.5) C10(-1.5,8.5) C11(-0.5,8.5) C12(0.5,8.5) C13(1.5,8.5) C14(2.5,8.5) C15(3.5,8.5) C16(4.5,8.5) C17(5.5,8.5) C18(6.5,8.5) C19(7.5,8.5) C20(8.5,8.5) C21(9.5,8.5) C22(10.5,8.5) D1(-10.5,7.5) D2(-9.5,7.5) D3(-8.5,7.5) D4(-7.5,7.5) D5(-6.5,7.5) D6(-5.5,7.5) D7(-4.5,7.5) D8(-3.5,7.5) D9(-2.5,7.5) D10(-1.5,7.5) D11(-0.5,7.5) D12(0.5,7.5) D13(1.5,7.5) D14(2.5,7.5) D15(3.5,7.5) D16(4.5,7.5) D17(5.5,7.5) D18(6.5,7.5) D19(7.5,7.5) D20(8.5,7.5) D21(9.5,7.5) D22(10.5,7.5) E1(-10.5,6.5) E2(-9.5,6.5) E3(-8.5,6.5) E4(-7.5,6.5) E5(-6.5,6.5) E6(-5.5,6.5) E7(-4.5,6.5) E8(-3.5,6.5) E9(-2.5,6.5) E10(-1.5,6.5) E11(-0.5,6.5) E12(0.5,6.5) E13(1.5,6.5) E14(2.5,6.5) E15(3.5,6.5) E16(4.5,6.5) E17(5.5,6.5) E18(6.5,6.5) E19(7.5,6.5) E20(8.5,6.5) E21(9.5,6.5) E22(10.5,6.5) F1(-10.5,5.5) F2(-9.5,5.5) F3(-8.5,5.5) F4(-7.5,5.5) F5(-6.5,5.5) F6(-5.5,5.5) F7(-4.5,5.5) F8(-3.5,5.5) F9(-2.5,5.5) F10(-1.5,5.5) F11(-0.5,5.5) F12(0.5,5.5) F13(1.5,5.5) F14(2.5,5.5) F15(3.5,5.5) F16(4.5,5.5) F17(5.5,5.5) F18(6.5,5.5) F19(7.5,5.5) F20(8.5,5.5) F21(9.5,5.5) F22(10.5,5.5) G1(-10.5,4.5) G2(-9.5,4.5) G3(-8.5,4.5) G4(-7.5,4.5) G5(-6.5,4.5) G6(-5.5,4.5) G7(-4.5,4.5) G8(-3.5,4.5) G9(-2.5,4.5) G10(-1.5,4.5) G11(-0.5,4.5) G12(0.5,4.5) G13(1.5,4.5) G14(2.5,4.5) G15(3.5,4.5) G16(4.5,4.5) G17(5.5,4.5) G18(6.5,4.5) G19(7.5,4.5) G20(8.5,4.5) G21(9.5,4.5) G22(10.5,4.5) H1(-10.5,3.5) H2(-9.5,3.5) H3(-8.5,3.5) H4(-7.5,3.5) H5(-6.5,3.5) H6(-5.5,3.5) H7(-4.5,3.5) H8(-3.5,3.5) H9(-2.5,3.5) H10(-1.5,3.5) H11(-0.5,3.5) H12(0.5,3.5) H13(1.5,3.5) H14(2.5,3.5) H15(3.5,3.5) H16(4.5,3.5) H17(5.5,3.5) H18(6.5,3.5) H19(7.5,3.5) H20(8.5,3.5) H21(9.5,3.5) H22(10.5,3.5) J1(-10.5,2.5) J2(-9.5,2.5) J3(-8.5,2.5) J4(-7.5,2.5) J5(-6.5,2.5) J6(-5.5,2.5) J7(-4.5,2.5) J8(-3.5,2.5) J9(-2.5,2.5) J10(-1.5,2.5) J11(-0.5,2.5) J12(0.5,2.5) J13(1.5,2.5) J14(2.5,2.5) J15(3.5,2.5) J16(4.5,2.5) J17(5.5,2.5) J18(6.5,2.5) J19(7.5,2.5) J20(8.5,2.5) J21(9.5,2.5) J22(10.5,2.5) K1(-10.5,1.5) K2(-9.5,1.5) K3(-8.5,1.5) K4(-7.5,1.5) K5(-6.5,1.5) K6(-5.5,1.5) K7(-4.5,1.5) K8(-3.5,1.5) K9(-2.5,1.5) K10(-1.5,1.5) K11(-0.5,1.5) K12(0.5,1.5) K13(1.5,1.5) K14(2.5,1.5) K15(3.5,1.5) K16(4.5,1.5) K17(5.5,1.5) K18(6.5,1.5) K19(7.5,1.5) K20(8.5,1.5) K21(9.5,1.5) K22(10.5,1.5) L1(-10.5,0.5) L2(-9.5,0.5) L3(-8.5,0.5) L4(-7.5,0.5) L5(-6.5,0.5) L6(-5.5,0.5) L7(-4.5,0.5) L8(-3.5,0.5) L9(-2.5,0.5) L10(-1.5,0.5) L11(-0.5,0.5) L12(0.5,0.5) L13(1.5,0.5) L14(2.5,0.5) L15(3.5,0.5) L16(4.5,0.5) L17(5.5,0.5) L18(6.5,0.5) L19(7.5,0.5) L20(8.5,0.5) L21(9.5,0.5) L22(10.5,0.5) M1(-10.5,-0.5) M2(-9.5,-0.5) M3(-8.5,-0.5) M4(-7.5,-0.5) M5(-6.5,-0.5) M6(-5.5,-0.5) M7(-4.5,-0.5) M8(-3.5,-0.5) M9(-2.5,-0.5) M10(-1.5,-0.5) M11(-0.5,-0.5) M12(0.5,-0.5) M13(1.5,-0.5) M14(2.5,-0.5) M15(3.5,-0.5) M16(4.5,-0.5) M17(5.5,-0.5) M18(6.5,-0.5) M19(7.5,-0.5) M20(8.5,-0.5) M21(9.5,-0.5) M22(10.5,-0.5) N1(-10.5,-1.5) N2(-9.5,-1.5) N3(-8.5,-1.5) N4(-7.5,-1.5) N5(-6.5,-1.5) N6(-5.5,-1.5) N7(-4.5,-1.5) N8(-3.5,-1.5) N9(-2.5,-1.5) N10(-1.5,-1.5) N11(-0.5,-1.5) N12(0.5,-1.5) N13(1.5,-1.5) N14(2.5,-1.5) N15(3.5,-1.5) N16(4.5,-1.5) N17(5.5,-1.5) N18(6.5,-1.5) N19(7.5,-1.5) N20(8.5,-1.5) N21(9.5,-1.5) N22(10.5,-1.5) P1(-10.5,-2.5) P2(-9.5,-2.5) P3(-8.5,-2.5) P4(-7.5,-2.5) P5(-6.5,-2.5) P6(-5.5,-2.5) P7(-4.5,-2.5) P8(-3.5,-2.5) P9(-2.5,-2.5) P10(-1.5,-2.5) P11(-0.5,-2.5) P12(0.5,-2.5) P13(1.5,-2.5) P14(2.5,-2.5) P15(3.5,-2.5) P16(4.5,-2.5) P17(5.5,-2.5) P18(6.5,-2.5) P19(7.5,-2.5) P20(8.5,-2.5) P21(9.5,-2.5) P22(10.5,-2.5) R1(-10.5,-3.5) R2(-9.5,-3.5) R3(-8.5,-3.5) R4(-7.5,-3.5) R5(-6.5,-3.5) R6(-5.5,-3.5) R7(-4.5,-3.5) R8(-3.5,-3.5) R9(-2.5,-3.5) R10(-1.5,-3.5) R11(-0.5,-3.5) R12(0.5,-3.5) R13(1.5,-3.5) R14(2.5,-3.5) R15(3.5,-3.5) R16(4.5,-3.5) R17(5.5,-3.5) R18(6.5,-3.5) R19(7.5,-3.5) R20(8.5,-3.5) R21(9.5,-3.5) R22(10.5,-3.5) T1(-10.5,-4.5) T2(-9.5,-4.5) T3(-8.5,-4.5) T4(-7.5,-4.5) T5(-6.5,-4.5) T6(-5.5,-4.5) T7(-4.5,-4.5) T8(-3.5,-4.5) T9(-2.5,-4.5) T10(-1.5,-4.5) T11(-0.5,-4.5) T12(0.5,-4.5) T13(1.5,-4.5) T14(2.5,-4.5) T15(3.5,-4.5) T16(4.5,-4.5) T17(5.5,-4.5) T18(6.5,-4.5) T19(7.5,-4.5) T20(8.5,-4.5) T21(9.5,-4.5) T22(10.5,-4.5) U1(-10.5,-5.5) U2(-9.5,-5.5) U3(-8.5,-5.5) U4(-7.5,-5.5) U5(-6.5,-5.5) U6(-5.5,-5.5) U7(-4.5,-5.5) U8(-3.5,-5.5) U9(-2.5,-5.5) U10(-1.5,-5.5) U11(-0.5,-5.5) U12(0.5,-5.5) U13(1.5,-5.5) U14(2.5,-5.5) U15(3.5,-5.5) U16(4.5,-5.5) U17(5.5,-5.5) U18(6.5,-5.5) U19(7.5,-5.5) U20(8.5,-5.5) U21(9.5,-5.5) U22(10.5,-5.5) V1(-10.5,-6.5) V2(-9.5,-6.5) V3(-8.5,-6.5) V4(-7.5,-6.5) V5(-6.5,-6.5) V6(-5.5,-6.5) V7(-4.5,-6.5) V8(-3.5,-6.5) V9(-2.5,-6.5) V10(-1.5,-6.5) V11(-0.5,-6.5) V12(0.5,-6.5) V13(1.5,-6.5) V14(2.5,-6.5) V15(3.5,-6.5) V16(4.5,-6.5) V17(5.5,-6.5) V18(6.5,-6.5) V19(7.5,-6.5) V20(8.5,-6.5) V21(9.5,-6.5) V22(10.5,-6.5) W1(-10.5,-7.5) W2(-9.5,-7.5) W3(-8.5,-7.5) W4(-7.5,-7.5) W5(-6.5,-7.5) W6(-5.5,-7.5) W7(-4.5,-7.5) W8(-3.5,-7.5) W9(-2.5,-7.5) W10(-1.5,-7.5) W11(-0.5,-7.5) W12(0.5,-7.5) W13(1.5,-7.5) W14(2.5,-7.5) W15(3.5,-7.5) W16(4.5,-7.5) W17(5.5,-7.5) W18(6.5,-7.5) W19(7.5,-7.5) W20(8.5,-7.5) W21(9.5,-7.5) W22(10.5,-7.5) Y1(-10.5,-8.5) Y2(-9.5,-8.5) Y3(-8.5,-8.5) Y4(-7.5,-8.5) Y5(-6.5,-8.5) Y6(-5.5,-8.5) Y7(-4.5,-8.5) Y8(-3.5,-8.5) Y9(-2.5,-8.5) Y10(-1.5,-8.5) Y11(-0.5,-8.5) Y12(0.5,-8.5) Y13(1.5,-8.5) Y14(2.5,-8.5) Y15(3.5,-8.5) Y16(4.5,-8.5) Y17(5.5,-8.5) Y18(6.5,-8.5) Y19(7.5,-8.5) Y20(8.5,-8.5) Y21(9.5,-8.5) Y22(10.5,-8.5)
Top Overlay:
  circle w0.25: c-12.15,10.5 r0.125
  region: -10.5,11.5 -11.5,10.5 -11.5,11.5
  lines w0.2: -11.5,10.5 -10.5,11.5 ; -11.5,-11.5 -11.5,11.5 11.5,11.5 11.5,-11.5 -11.5,-11.5
Mechanical 13:
  lines w0.1: -11.5,-11.5 -11.5,11.5 11.5,11.5 11.5,-11.5 -11.5,-11.5
Mechanical 15:
  lines w0.1: -0.5,0 0.5,0 ; 0,-0.5 0,0.5 ; -12.5,-12.5 -12.5,12.5 12.5,12.5 12.5,-12.5 -12.5,-12.5
3D body: height 2.6, standoff 0, extent -11.5,-11.5 11.5,11.5

## FGG676 [mm] "676-Ball Fine Pitch Ball Grid Array (FGG676) - Pb-Free"
height 2.6
pads (676):
  round 0.5 smd: A1(-12.5,12.5) A2(-11.5,12.5) A3(-10.5,12.5) A4(-9.5,12.5) A5(-8.5,12.5) A6(-7.5,12.5) A7(-6.5,12.5) A8(-5.5,12.5) A9(-4.5,12.5) A10(-3.5,12.5) A11(-2.5,12.5) A12(-1.5,12.5) A13(-0.5,12.5) A14(0.5,12.5) A15(1.5,12.5) A16(2.5,12.5) A17(3.5,12.5) A18(4.5,12.5) A19(5.5,12.5) A20(6.5,12.5) A21(7.5,12.5) A22(8.5,12.5) A23(9.5,12.5) A24(10.5,12.5) A25(11.5,12.5) A26(12.5,12.5) AA1(-12.5,-7.5) AA2(-11.5,-7.5) AA3(-10.5,-7.5) AA4(-9.5,-7.5) AA5(-8.5,-7.5) AA6(-7.5,-7.5) AA7(-6.5,-7.5) AA8(-5.5,-7.5) AA9(-4.5,-7.5) AA10(-3.5,-7.5) AA11(-2.5,-7.5) AA12(-1.5,-7.5) AA13(-0.5,-7.5) AA14(0.5,-7.5) AA15(1.5,-7.5) AA16(2.5,-7.5) AA17(3.5,-7.5) AA18(4.5,-7.5) AA19(5.5,-7.5) AA20(6.5,-7.5) AA21(7.5,-7.5) AA22(8.5,-7.5) AA23(9.5,-7.5) AA24(10.5,-7.5) AA25(11.5,-7.5) AA26(12.5,-7.5) AB1(-12.5,-8.5) AB2(-11.5,-8.5) AB3(-10.5,-8.5) AB4(-9.5,-8.5) AB5(-8.5,-8.5) AB6(-7.5,-8.5) AB7(-6.5,-8.5) AB8(-5.5,-8.5) AB9(-4.5,-8.5) AB10(-3.5,-8.5) AB11(-2.5,-8.5) AB12(-1.5,-8.5) AB13(-0.5,-8.5) AB14(0.5,-8.5) AB15(1.5,-8.5) AB16(2.5,-8.5) AB17(3.5,-8.5) AB18(4.5,-8.5) AB19(5.5,-8.5) AB20(6.5,-8.5) AB21(7.5,-8.5) AB22(8.5,-8.5) AB23(9.5,-8.5) AB24(10.5,-8.5) AB25(11.5,-8.5) AB26(12.5,-8.5) AC1(-12.5,-9.5) AC2(-11.5,-9.5) AC3(-10.5,-9.5) AC4(-9.5,-9.5) AC5(-8.5,-9.5) AC6(-7.5,-9.5) AC7(-6.5,-9.5) AC8(-5.5,-9.5) AC9(-4.5,-9.5) AC10(-3.5,-9.5) AC11(-2.5,-9.5) AC12(-1.5,-9.5) AC13(-0.5,-9.5) AC14(0.5,-9.5) AC15(1.5,-9.5) AC16(2.5,-9.5) AC17(3.5,-9.5) AC18(4.5,-9.5) AC19(5.5,-9.5) AC20(6.5,-9.5) AC21(7.5,-9.5) AC22(8.5,-9.5) AC23(9.5,-9.5) AC24(10.5,-9.5) AC25(11.5,-9.5) AC26(12.5,-9.5) AD1(-12.5,-10.5) AD2(-11.5,-10.5) AD3(-10.5,-10.5) AD4(-9.5,-10.5) AD5(-8.5,-10.5) AD6(-7.5,-10.5) AD7(-6.5,-10.5) AD8(-5.5,-10.5) AD9(-4.5,-10.5) AD10(-3.5,-10.5) AD11(-2.5,-10.5) AD12(-1.5,-10.5) AD13(-0.5,-10.5) AD14(0.5,-10.5) AD15(1.5,-10.5) AD16(2.5,-10.5) AD17(3.5,-10.5) AD18(4.5,-10.5) AD19(5.5,-10.5) AD20(6.5,-10.5) AD21(7.5,-10.5) AD22(8.5,-10.5) AD23(9.5,-10.5) AD24(10.5,-10.5) AD25(11.5,-10.5) AD26(12.5,-10.5) AE1(-12.5,-11.5) AE2(-11.5,-11.5) AE3(-10.5,-11.5) AE4(-9.5,-11.5) AE5(-8.5,-11.5) AE6(-7.5,-11.5) AE7(-6.5,-11.5) AE8(-5.5,-11.5) AE9(-4.5,-11.5) AE10(-3.5,-11.5) AE11(-2.5,-11.5) AE12(-1.5,-11.5) AE13(-0.5,-11.5) AE14(0.5,-11.5) AE15(1.5,-11.5) AE16(2.5,-11.5) AE17(3.5,-11.5) AE18(4.5,-11.5) AE19(5.5,-11.5) AE20(6.5,-11.5) AE21(7.5,-11.5) AE22(8.5,-11.5) AE23(9.5,-11.5) AE24(10.5,-11.5) AE25(11.5,-11.5) AE26(12.5,-11.5) AF1(-12.5,-12.5) AF2(-11.5,-12.5) AF3(-10.5,-12.5) AF4(-9.5,-12.5) AF5(-8.5,-12.5) AF6(-7.5,-12.5) AF7(-6.5,-12.5) AF8(-5.5,-12.5) AF9(-4.5,-12.5) AF10(-3.5,-12.5) AF11(-2.5,-12.5) AF12(-1.5,-12.5) AF13(-0.5,-12.5) AF14(0.5,-12.5) AF15(1.5,-12.5) AF16(2.5,-12.5) AF17(3.5,-12.5) AF18(4.5,-12.5) AF19(5.5,-12.5) AF20(6.5,-12.5) AF21(7.5,-12.5) AF22(8.5,-12.5) AF23(9.5,-12.5) AF24(10.5,-12.5) AF25(11.5,-12.5) AF26(12.5,-12.5) B1(-12.5,11.5) B2(-11.5,11.5) B3(-10.5,11.5) B4(-9.5,11.5) B5(-8.5,11.5) B6(-7.5,11.5) B7(-6.5,11.5) B8(-5.5,11.5) B9(-4.5,11.5) B10(-3.5,11.5) B11(-2.5,11.5) B12(-1.5,11.5) B13(-0.5,11.5) B14(0.5,11.5) B15(1.5,11.5) B16(2.5,11.5) B17(3.5,11.5) B18(4.5,11.5) B19(5.5,11.5) B20(6.5,11.5) B21(7.5,11.5) B22(8.5,11.5) B23(9.5,11.5) B24(10.5,11.5) B25(11.5,11.5) B26(12.5,11.5) C1(-12.5,10.5) C2(-11.5,10.5) C3(-10.5,10.5) C4(-9.5,10.5) C5(-8.5,10.5) C6(-7.5,10.5) C7(-6.5,10.5) C8(-5.5,10.5) C9(-4.5,10.5) C10(-3.5,10.5) C11(-2.5,10.5) C12(-1.5,10.5) C13(-0.5,10.5) C14(0.5,10.5) C15(1.5,10.5) C16(2.5,10.5) C17(3.5,10.5) C18(4.5,10.5) C19(5.5,10.5) C20(6.5,10.5) C21(7.5,10.5) C22(8.5,10.5) C23(9.5,10.5) C24(10.5,10.5) C25(11.5,10.5) C26(12.5,10.5) D1(-12.5,9.5) D2(-11.5,9.5) D3(-10.5,9.5) D4(-9.5,9.5) D5(-8.5,9.5) D6(-7.5,9.5) D7(-6.5,9.5) D8(-5.5,9.5) D9(-4.5,9.5) D10(-3.5,9.5) D11(-2.5,9.5) D12(-1.5,9.5) D13(-0.5,9.5) D14(0.5,9.5) D15(1.5,9.5) D16(2.5,9.5) D17(3.5,9.5) D18(4.5,9.5) D19(5.5,9.5) D20(6.5,9.5) D21(7.5,9.5) D22(8.5,9.5) D23(9.5,9.5) D24(10.5,9.5) D25(11.5,9.5) D26(12.5,9.5) E1(-12.5,8.5) E2(-11.5,8.5) E3(-10.5,8.5) E4(-9.5,8.5) E5(-8.5,8.5) E6(-7.5,8.5) E7(-6.5,8.5) E8(-5.5,8.5) E9(-4.5,8.5) E10(-3.5,8.5) E11(-2.5,8.5) E12(-1.5,8.5) E13(-0.5,8.5) E14(0.5,8.5) E15(1.5,8.5) E16(2.5,8.5) E17(3.5,8.5) E18(4.5,8.5) E19(5.5,8.5) E20(6.5,8.5) E21(7.5,8.5) E22(8.5,8.5) E23(9.5,8.5) E24(10.5,8.5) E25(11.5,8.5) E26(12.5,8.5) F1(-12.5,7.5) F2(-11.5,7.5) F3(-10.5,7.5) F4(-9.5,7.5) F5(-8.5,7.5) F6(-7.5,7.5) F7(-6.5,7.5) F8(-5.5,7.5) F9(-4.5,7.5) F10(-3.5,7.5) F11(-2.5,7.5) F12(-1.5,7.5) F13(-0.5,7.5) F14(0.5,7.5) F15(1.5,7.5) F16(2.5,7.5) F17(3.5,7.5) F18(4.5,7.5) F19(5.5,7.5) F20(6.5,7.5) F21(7.5,7.5) F22(8.5,7.5) F23(9.5,7.5) F24(10.5,7.5) F25(11.5,7.5) F26(12.5,7.5) G1(-12.5,6.5) G2(-11.5,6.5) G3(-10.5,6.5) G4(-9.5,6.5) G5(-8.5,6.5) G6(-7.5,6.5) G7(-6.5,6.5) G8(-5.5,6.5) G9(-4.5,6.5) G10(-3.5,6.5) G11(-2.5,6.5) G12(-1.5,6.5) G13(-0.5,6.5) G14(0.5,6.5) G15(1.5,6.5) G16(2.5,6.5) G17(3.5,6.5) G18(4.5,6.5) G19(5.5,6.5) G20(6.5,6.5) G21(7.5,6.5) G22(8.5,6.5) G23(9.5,6.5) G24(10.5,6.5) G25(11.5,6.5) G26(12.5,6.5) H1(-12.5,5.5) H2(-11.5,5.5) H3(-10.5,5.5) H4(-9.5,5.5) H5(-8.5,5.5) H6(-7.5,5.5) H7(-6.5,5.5) H8(-5.5,5.5) H9(-4.5,5.5) H10(-3.5,5.5) H11(-2.5,5.5) H12(-1.5,5.5) H13(-0.5,5.5) H14(0.5,5.5) H15(1.5,5.5) H16(2.5,5.5) H17(3.5,5.5) H18(4.5,5.5) H19(5.5,5.5) H20(6.5,5.5) H21(7.5,5.5) H22(8.5,5.5) H23(9.5,5.5) H24(10.5,5.5) H25(11.5,5.5) H26(12.5,5.5) J1(-12.5,4.5) J2(-11.5,4.5) J3(-10.5,4.5) J4(-9.5,4.5) J5(-8.5,4.5) J6(-7.5,4.5) J7(-6.5,4.5) J8(-5.5,4.5) J9(-4.5,4.5) J10(-3.5,4.5) J11(-2.5,4.5) J12(-1.5,4.5) J13(-0.5,4.5) J14(0.5,4.5) J15(1.5,4.5) J16(2.5,4.5) J17(3.5,4.5) J18(4.5,4.5) J19(5.5,4.5) J20(6.5,4.5) J21(7.5,4.5) J22(8.5,4.5) J23(9.5,4.5) J24(10.5,4.5) J25(11.5,4.5) J26(12.5,4.5) K1(-12.5,3.5) K2(-11.5,3.5) K3(-10.5,3.5) K4(-9.5,3.5) K5(-8.5,3.5) K6(-7.5,3.5) K7(-6.5,3.5) K8(-5.5,3.5) K9(-4.5,3.5) K10(-3.5,3.5) K11(-2.5,3.5) K12(-1.5,3.5) K13(-0.5,3.5) K14(0.5,3.5) K15(1.5,3.5) K16(2.5,3.5) K17(3.5,3.5) K18(4.5,3.5) K19(5.5,3.5) K20(6.5,3.5) K21(7.5,3.5) K22(8.5,3.5) K23(9.5,3.5) K24(10.5,3.5) K25(11.5,3.5) K26(12.5,3.5) L1(-12.5,2.5) L2(-11.5,2.5) L3(-10.5,2.5) L4(-9.5,2.5) L5(-8.5,2.5) L6(-7.5,2.5) L7(-6.5,2.5) L8(-5.5,2.5) L9(-4.5,2.5) L10(-3.5,2.5) L11(-2.5,2.5) L12(-1.5,2.5) L13(-0.5,2.5) L14(0.5,2.5) L15(1.5,2.5) L16(2.5,2.5) L17(3.5,2.5) L18(4.5,2.5) L19(5.5,2.5) L20(6.5,2.5) L21(7.5,2.5) L22(8.5,2.5) L23(9.5,2.5) L24(10.5,2.5) L25(11.5,2.5) L26(12.5,2.5) M1(-12.5,1.5) M2(-11.5,1.5) M3(-10.5,1.5) M4(-9.5,1.5) M5(-8.5,1.5) M6(-7.5,1.5) M7(-6.5,1.5) M8(-5.5,1.5) M9(-4.5,1.5) M10(-3.5,1.5) M11(-2.5,1.5) M12(-1.5,1.5) M13(-0.5,1.5) M14(0.5,1.5) M15(1.5,1.5) M16(2.5,1.5) M17(3.5,1.5) M18(4.5,1.5) M19(5.5,1.5) M20(6.5,1.5) M21(7.5,1.5) M22(8.5,1.5) M23(9.5,1.5) M24(10.5,1.5) M25(11.5,1.5) M26(12.5,1.5) N1(-12.5,0.5) N2(-11.5,0.5) N3(-10.5,0.5) N4(-9.5,0.5) N5(-8.5,0.5) N6(-7.5,0.5) N7(-6.5,0.5) N8(-5.5,0.5) N9(-4.5,0.5) N10(-3.5,0.5) N11(-2.5,0.5) N12(-1.5,0.5) N13(-0.5,0.5) N14(0.5,0.5) N15(1.5,0.5) N16(2.5,0.5) N17(3.5,0.5) N18(4.5,0.5) N19(5.5,0.5) N20(6.5,0.5) N21(7.5,0.5) N22(8.5,0.5) N23(9.5,0.5) N24(10.5,0.5) N25(11.5,0.5) N26(12.5,0.5) P1(-12.5,-0.5) P2(-11.5,-0.5) P3(-10.5,-0.5) P4(-9.5,-0.5) P5(-8.5,-0.5) P6(-7.5,-0.5) P7(-6.5,-0.5) P8(-5.5,-0.5) P9(-4.5,-0.5) P10(-3.5,-0.5) P11(-2.5,-0.5) P12(-1.5,-0.5) P13(-0.5,-0.5) P14(0.5,-0.5) P15(1.5,-0.5) P16(2.5,-0.5) P17(3.5,-0.5) P18(4.5,-0.5) P19(5.5,-0.5) P20(6.5,-0.5) P21(7.5,-0.5) P22(8.5,-0.5) P23(9.5,-0.5) P24(10.5,-0.5) P25(11.5,-0.5) P26(12.5,-0.5) R1(-12.5,-1.5) R2(-11.5,-1.5) R3(-10.5,-1.5) R4(-9.5,-1.5) R5(-8.5,-1.5) R6(-7.5,-1.5) R7(-6.5,-1.5) R8(-5.5,-1.5) R9(-4.5,-1.5) R10(-3.5,-1.5) R11(-2.5,-1.5) R12(-1.5,-1.5) R13(-0.5,-1.5) R14(0.5,-1.5) R15(1.5,-1.5) R16(2.5,-1.5) R17(3.5,-1.5) R18(4.5,-1.5) R19(5.5,-1.5) R20(6.5,-1.5) R21(7.5,-1.5) R22(8.5,-1.5) R23(9.5,-1.5) R24(10.5,-1.5) R25(11.5,-1.5) R26(12.5,-1.5) T1(-12.5,-2.5) T2(-11.5,-2.5) T3(-10.5,-2.5) T4(-9.5,-2.5) T5(-8.5,-2.5) T6(-7.5,-2.5) T7(-6.5,-2.5) T8(-5.5,-2.5) T9(-4.5,-2.5) T10(-3.5,-2.5) T11(-2.5,-2.5) T12(-1.5,-2.5) T13(-0.5,-2.5) T14(0.5,-2.5) T15(1.5,-2.5) T16(2.5,-2.5) T17(3.5,-2.5) T18(4.5,-2.5) T19(5.5,-2.5) T20(6.5,-2.5) T21(7.5,-2.5) T22(8.5,-2.5) T23(9.5,-2.5) T24(10.5,-2.5) T25(11.5,-2.5) T26(12.5,-2.5) U1(-12.5,-3.5) U2(-11.5,-3.5) U3(-10.5,-3.5) U4(-9.5,-3.5) U5(-8.5,-3.5) U6(-7.5,-3.5) U7(-6.5,-3.5) U8(-5.5,-3.5) U9(-4.5,-3.5) U10(-3.5,-3.5) U11(-2.5,-3.5) U12(-1.5,-3.5) U13(-0.5,-3.5) U14(0.5,-3.5) U15(1.5,-3.5) U16(2.5,-3.5) U17(3.5,-3.5) U18(4.5,-3.5) U19(5.5,-3.5) U20(6.5,-3.5) U21(7.5,-3.5) U22(8.5,-3.5) U23(9.5,-3.5) U24(10.5,-3.5) U25(11.5,-3.5) U26(12.5,-3.5) V1(-12.5,-4.5) V2(-11.5,-4.5) V3(-10.5,-4.5) V4(-9.5,-4.5) V5(-8.5,-4.5) V6(-7.5,-4.5) V7(-6.5,-4.5) V8(-5.5,-4.5) V9(-4.5,-4.5) V10(-3.5,-4.5) V11(-2.5,-4.5) V12(-1.5,-4.5) V13(-0.5,-4.5) V14(0.5,-4.5) V15(1.5,-4.5) V16(2.5,-4.5) V17(3.5,-4.5) V18(4.5,-4.5) V19(5.5,-4.5) V20(6.5,-4.5) V21(7.5,-4.5) V22(8.5,-4.5) V23(9.5,-4.5) V24(10.5,-4.5) V25(11.5,-4.5) V26(12.5,-4.5) W1(-12.5,-5.5) W2(-11.5,-5.5) W3(-10.5,-5.5) W4(-9.5,-5.5) W5(-8.5,-5.5) W6(-7.5,-5.5) W7(-6.5,-5.5) W8(-5.5,-5.5) W9(-4.5,-5.5) W10(-3.5,-5.5) W11(-2.5,-5.5) W12(-1.5,-5.5) W13(-0.5,-5.5) W14(0.5,-5.5) W15(1.5,-5.5) W16(2.5,-5.5) W17(3.5,-5.5) W18(4.5,-5.5) W19(5.5,-5.5) W20(6.5,-5.5) W21(7.5,-5.5) W22(8.5,-5.5) W23(9.5,-5.5) W24(10.5,-5.5) W25(11.5,-5.5) W26(12.5,-5.5) Y1(-12.5,-6.5) Y2(-11.5,-6.5) Y3(-10.5,-6.5) Y4(-9.5,-6.5) Y5(-8.5,-6.5) Y6(-7.5,-6.5) Y7(-6.5,-6.5) Y8(-5.5,-6.5) Y9(-4.5,-6.5) Y10(-3.5,-6.5) Y11(-2.5,-6.5) Y12(-1.5,-6.5) Y13(-0.5,-6.5) Y14(0.5,-6.5) Y15(1.5,-6.5) Y16(2.5,-6.5) Y17(3.5,-6.5) Y18(4.5,-6.5) Y19(5.5,-6.5) Y20(6.5,-6.5) Y21(7.5,-6.5) Y22(8.5,-6.5) Y23(9.5,-6.5) Y24(10.5,-6.5) Y25(11.5,-6.5) Y26(12.5,-6.5)
Top Overlay:
  circle w0.25: c-14.15,12.5 r0.125
  region: -12.5,13.5 -13.5,12.5 -13.5,13.5
  lines w0.2: -13.5,12.5 -12.5,13.5 ; -13.5,-13.5 13.5,-13.5 13.5,13.5 -13.5,13.5 -13.5,-13.5
Mechanical 13:
  lines w0.1: -13.5,-13.5 13.5,-13.5 13.5,13.5 -13.5,13.5 -13.5,-13.5
Mechanical 15:
  lines w0.1: -0.5,0 0.5,0 ; 0,-0.5 0,0.5 ; -14.5,-14.5 14.5,-14.5 14.5,14.5 -14.5,14.5 -14.5,-14.5
3D body: height 2.6, standoff 0, extent -13.5,-13.5 13.5,13.5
